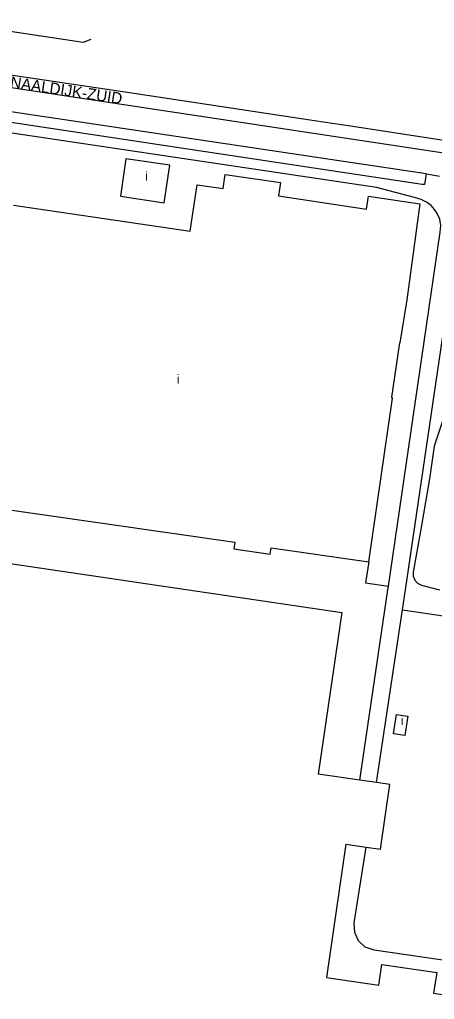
# Model space of a CAD drawing. Extents: x 162804 to 165059, y 381530 to 382901.
# Drawn here: x 164299.3 to 164482.2, y 382270.6 to 382702.5 of the extents above; entities that cross this region are included whole.
import ezdxf

# ---------------------------------------------------------------- set-up
doc = ezdxf.new("R2010")
doc.units = 0
for name, color, linetype in [('BLT_Basislijn', 7, 'Continuous'), ('BLT_Bebouwing', 7, 'Continuous'), ('BLT_Centroide', 7, 'Continuous'), ('BLT_Straatnaam', 7, 'Continuous')]:
    doc.layers.add(name, color=color, linetype=linetype)

msp = doc.modelspace()

# ---------------------------------------------------------------- linework, layer by layer
at = {"layer": 'BLT_Basislijn'}
for p, q in [((164301.17, 382677.11), (164259.97, 382683.29)), ((164345.82, 382670.47), (164301.17, 382677.11)), ((164478.56, 382634.47), (164224.63, 382672.41)), ((164429.26, 382657.92), (164345.82, 382670.47)), ((164445.23, 382655.47), (164429.26, 382657.92)), ((164500, 382647.13), (164445.23, 382655.47)), ((164478.56, 382634.47), (164480.53, 382634.15)), ((164480.53, 382634.15), (164484.47, 382633.52)), ((164449.3, 382367.23), (164461.71, 382451.07)), ((164456.73, 382366.15), (164468.09, 382442.31)), ((164468.09, 382442.31), (164585.3, 382425.23)), ((164446.83, 382304.26), (164452.18, 382337.67))]:
    msp.add_line(p, q, dxfattribs=at)
for points in [[(164330.71, 382693.74), (164327.27, 382692.4), (164259.86, 382702.49)], [(164491.16, 382642.9), (164235.25, 382681.52)], [(164478.56, 382634.47), (164477.83, 382629.84), (164476.83, 382629.84), (164234.87, 382666.25), (164187.08, 382673.32)], [(164478.94, 382621.91), (164476.38, 382623.2), (164473.37, 382624.1), (164456.64, 382628.41), (164284.02, 382654.13), (164187.08, 382668.45)], [(164461.95, 382452.73), (164484.8, 382608.74), (164484.99, 382611.71), (164484.52, 382614.56), (164483.42, 382617), (164482.27, 382618.79), (164480.7, 382620.6), (164478.94, 382621.91)], [(164469.38, 382451.07), (164492.17, 382605.91), (164493.07, 382609.42), (164494.77, 382612.41), (164496.95, 382614.93), (164500, 382617.05), (164502.18, 382617.97), (164504.57, 382618.64)], [(164486.66, 382528.14), (164482.16, 382514.5), (164480.06, 382500), (164476.45, 382479.46), (164472.85, 382458.93), (164472.87, 382457.18), (164473.55, 382455.38), (164474.71, 382454.02), (164476.46, 382453.24), (164484.49, 382451.07)], [(164453.22, 382463.45), (164451.86, 382454.14), (164461.95, 382452.73)], [(164461.71, 382451.07), (164461.95, 382452.73)], [(164468.09, 382442.31), (164469.38, 382451.07)], [(164565.36, 382284.4), (164564.48, 382281.56), (164562.31, 382279.11), (164559.68, 382277.73), (164557.96, 382277.44), (164556.39, 382277.61), (164455.7, 382292.21), (164451.69, 382293.55), (164448.74, 382296.38), (164447.07, 382300.08), (164446.83, 382304.26)]]:
    msp.add_lwpolyline(points, dxfattribs=at)
at = {"layer": 'BLT_Bebouwing'}
for p, q in [((164363.12, 382621.73), (164365.57, 382638.3)), ((164475.75, 382621.3), (164470.02, 382578.92)), ((164361.56, 382611.1), (164374.56, 382609.18)), ((164470.02, 382578.92), (164466.9, 382560.07)), ((164470.5, 382395.45), (164469.21, 382386.92)), ((164449.3, 382367.23), (164430.97, 382369.9)), ((164456.73, 382366.15), (164449.3, 382367.23)), ((164443.08, 382338.99), (164452.18, 382337.67))]:
    msp.add_line(p, q, dxfattribs=at)
for points in [[(164365.57, 382638.3), (164346.19, 382641.17), (164343.74, 382624.6), (164363.12, 382621.73)], [(164374.56, 382609.18), (164377.58, 382629.68), (164389.1, 382627.99), (164390.02, 382634.22), (164414.34, 382630.64), (164413.46, 382624.75), (164452.28, 382618.94), (164453.14, 382624.68), (164475.75, 382621.3)], [(164296.68, 382620.66), (164361.56, 382611.1)], [(164453.22, 382463.45), (164458.51, 382500), (164463.76, 382535.59), (164463.37, 382536.11), (164466.9, 382560.07)], [(164277.36, 382488.91), (164394.25, 382472.18), (164393.82, 382469.18), (164409.78, 382466.9), (164410.16, 382469.61), (164453.22, 382463.45)], [(164272, 382451.61), (164274.09, 382465.8), (164441.35, 382441.16), (164430.97, 382369.9)], [(164469.21, 382386.92), (164464.22, 382387.67), (164465.51, 382396.2), (164470.5, 382395.45)], [(164452.18, 382337.67), (164458.38, 382336.77), (164462.54, 382365.3), (164456.73, 382366.15)], [(164443.08, 382338.99), (164434.56, 382280.19), (164457.68, 382276.8)], [(164457.68, 382276.8), (164459.01, 382285.99), (164483.21, 382282.48), (164481.87, 382273.25), (164500.14, 382270.56)]]:
    msp.add_lwpolyline(points, dxfattribs=at)

# ---------------------------------------------------------------- texts
at = {"layer": 'BLT_Centroide'}
for p in [(164354.66, 382631.44), (164368.61, 382542.06), (164467.36, 382391.56)]:
    msp.add_text('i', height=4, dxfattribs=at).set_placement(p)
at = {"layer": 'BLT_Straatnaam'}
msp.add_text('KANAALDIJK-ZUID', height=4.9999, rotation=351.4309, dxfattribs=at).set_placement((164286.13, 382673.91))

doc.saveas('drawing.dxf')
